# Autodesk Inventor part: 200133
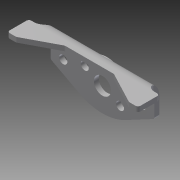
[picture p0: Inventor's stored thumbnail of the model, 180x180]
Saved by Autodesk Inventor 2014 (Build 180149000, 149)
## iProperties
Created: 2007-12
Part Number: 200133
Document SubType Name: Modeling
Designer: TH
Density: 7.85 g/cm^3
Mass: 53.4442 g
Surface Area: 55.5133 cm^2
Volume: 6.80817 cm^3
Material: Steel
Description: MOUNTING BRACKET
Appearance: Steel
Component Category: Lower Component
Author: TH
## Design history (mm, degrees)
sketch "Sketch1"
  geometry: L1 (-31.75, 0)-(31.75, 0); L2 (31.75, 0)-(31.75, -8); L3 (31.75, -8)-(40, -8); L4 (40, -8)-(40, -21.25); L5 (40, -21.25)-(34.5, -21.25); L6 (34.5, -21.25)-(15, -11); L7 (15, -11)-(-15, -11); L8 (-15, -11)-(-34.5, -21.25); L9 (-34.5, -21.25)-(-40, -21.25); L10 (-40, -21.25)-(-40, -8); L11 (-40, -8)-(-31.75, -8); L12 (-31.75, -8)-(-31.75, 0); 2 further points
  constraints: 24 end point, 7 parallel, 2 collinear, 1 coincident, 1 horizontal, 1 midpoint, 1 perpendicular
  dimensions: "d0" = 63.5 distance of L1.start L1.end; "d1" = 8 distance of L11.end L1.start; "d2" = 8.25 distance of L10.end L11.end; "d3" = 8.25 distance of L2.end L3.end (= d2); "d4" = 21.25 distance between parallel lines of L1 L5; "d5" = 30 distance of L6.end L7.end; "d6" = 15 horizontal distance of point (0, 0) L6.end (= 0.5 x d5); "d7" = 11 distance between parallel lines of L1 L7; "d8" = 5.5 distance of L4.end L5.end; "d9" = 5.5 distance of L8.end L9.end (= d8)
extrude "Extrusion1" new body sketch "Sketch1" distance "d10" = 3; taper "d11" = 0 deg
sketch "Sketch2"
  geometry: L1 (63.5, 3)-(0, 3) reference; L2 (0, 0)-(63.5, 0) reference; L3 (63.5, 0)-(63.5, 3) reference; L4 (63.5, 3)-(63.5, 19.5); L5 (63.5, 19.5)-(45.834, 28.893); L6 (0, 3)-(0, 19.5); L7 (0, 19.5)-(17.666, 28.893); A1 r 30 centre (31.75, 2.405) between (45.834, 28.893) and (17.666, 28.893); 1 further point
  constraints: 8 end point, 2 point on circle, 2 tangent, 1 centre point, 1 collinear, 1 parallel, 1 point on line
  dimensions: "d12" = 19.5 distance of L2.end L4.end; "d13" = 19.5 distance from line of L6.end L2 (= d12); "d14" = 62 deg angle of L4 L5; "d15" = 62 deg angle of L6 L7 (= d14); "d16" = 30 radius of A1
extrude "Extrusion2" join sketch "Sketch2" distance "d17" = 3; taper "d18" = 0 deg
fillet "Fillet1" dims "d19" = 5
fillet "Fillet2" dims "d20" = 8
fillet "Fillet3" dims "d21" = 5
fillet "Fillet4" dims "d22" = 1.5
sketch "Sketch3"
  geometry: L1 (31.75, 5.595)-(-31.75, 5.595) reference; L2 (0, 5.595)-(0, 30); L3 (-9.998, 5.595)-(9.998, 5.595); A1 r 30 centre (0, 0) between (14.084, 26.488) and (-14.084, 26.488) reference; A2 r 14 centre (0, 15.395) between (-9.998, 5.595) and (9.998, 5.595); 2 further points
  constraints: 4 end point, 3 point on circle, 3 point on line, 1 centre point, 1 coincident, 1 midpoint, 1 perpendicular
  dimensions: "d23" = 9.8 distance from line of point (0, 15.395) L1; "d24" = 28 diameter of A2
extrude "Extrusion3" join sketch "Sketch3" distance "d25" = 2; taper "d26" = 0 deg
sketch "Sketch4"
  geometry: L1 (0, -8)-(63.5, -8) reference; C1 r 13 at (31.75, -17.8); A1 r 14 centre (31.75, -17.8) between (41.748, -8) and (21.752, -8) reference; 1 further point
  constraints: 1 centre point, 1 coincident
  dimensions: "d31" = 1 radial gap between concentric circles of A1 C1
extrude "Extrusion4" cut sketch "Sketch4" distance "d27" = 4; taper "d28" = 0 deg
fillet "Fillet5" dims "d29" = 0.5
fillet "Fillet6" dims "d30" = 0.5
sketch "Sketch5"
  geometry: C1 r 5.25 at (0, 15.395); A1 r 13.5 centre (0, 15.395) between (-9.285, 5.595) and (9.285, 5.595) reference; 5 further points
  constraints: 1 centre point, 1 coincident
  dimensions: "d32" = 10.5 diameter of C1; "d33" = 10.8 horizontal distance of point (10.8, 20.645) A1.centre; "d34" = 24 horizontal distance of point (24, 13.461) A1.centre; "d35" = 10.8 horizontal distance of point (-10.8, 10.145) A1.centre; "d36" = 24 horizontal distance of point (-24, 13.46) A1.centre; "d37" = 1.93523 vertical distance of A1.centre point (-24, 13.46); "d38" = 5.25 vertical distance of A1.centre point (-10.8, 10.145); "d39" = 5.25 vertical distance of point (10.8, 20.645) A1.centre; "d40" = 1.9347 vertical distance of A1.centre point (24, 13.461)
extrude "Extrusion5" cut sketch "Sketch5" stored distance "d41" = 2; taper "d42" = 0 deg
hole "Hole1" sketch "Sketch5" diameter "d43" = 5; stored, may be unused: countersink angle "d47" = 90 deg, drill point angle "d49" = 118 deg; dims "d44" = 6, "d45" = 4, "d46" = 2, "d48" = 8
fillet "Fillet7" dims "d50" = 1.5
body "Solid1"
